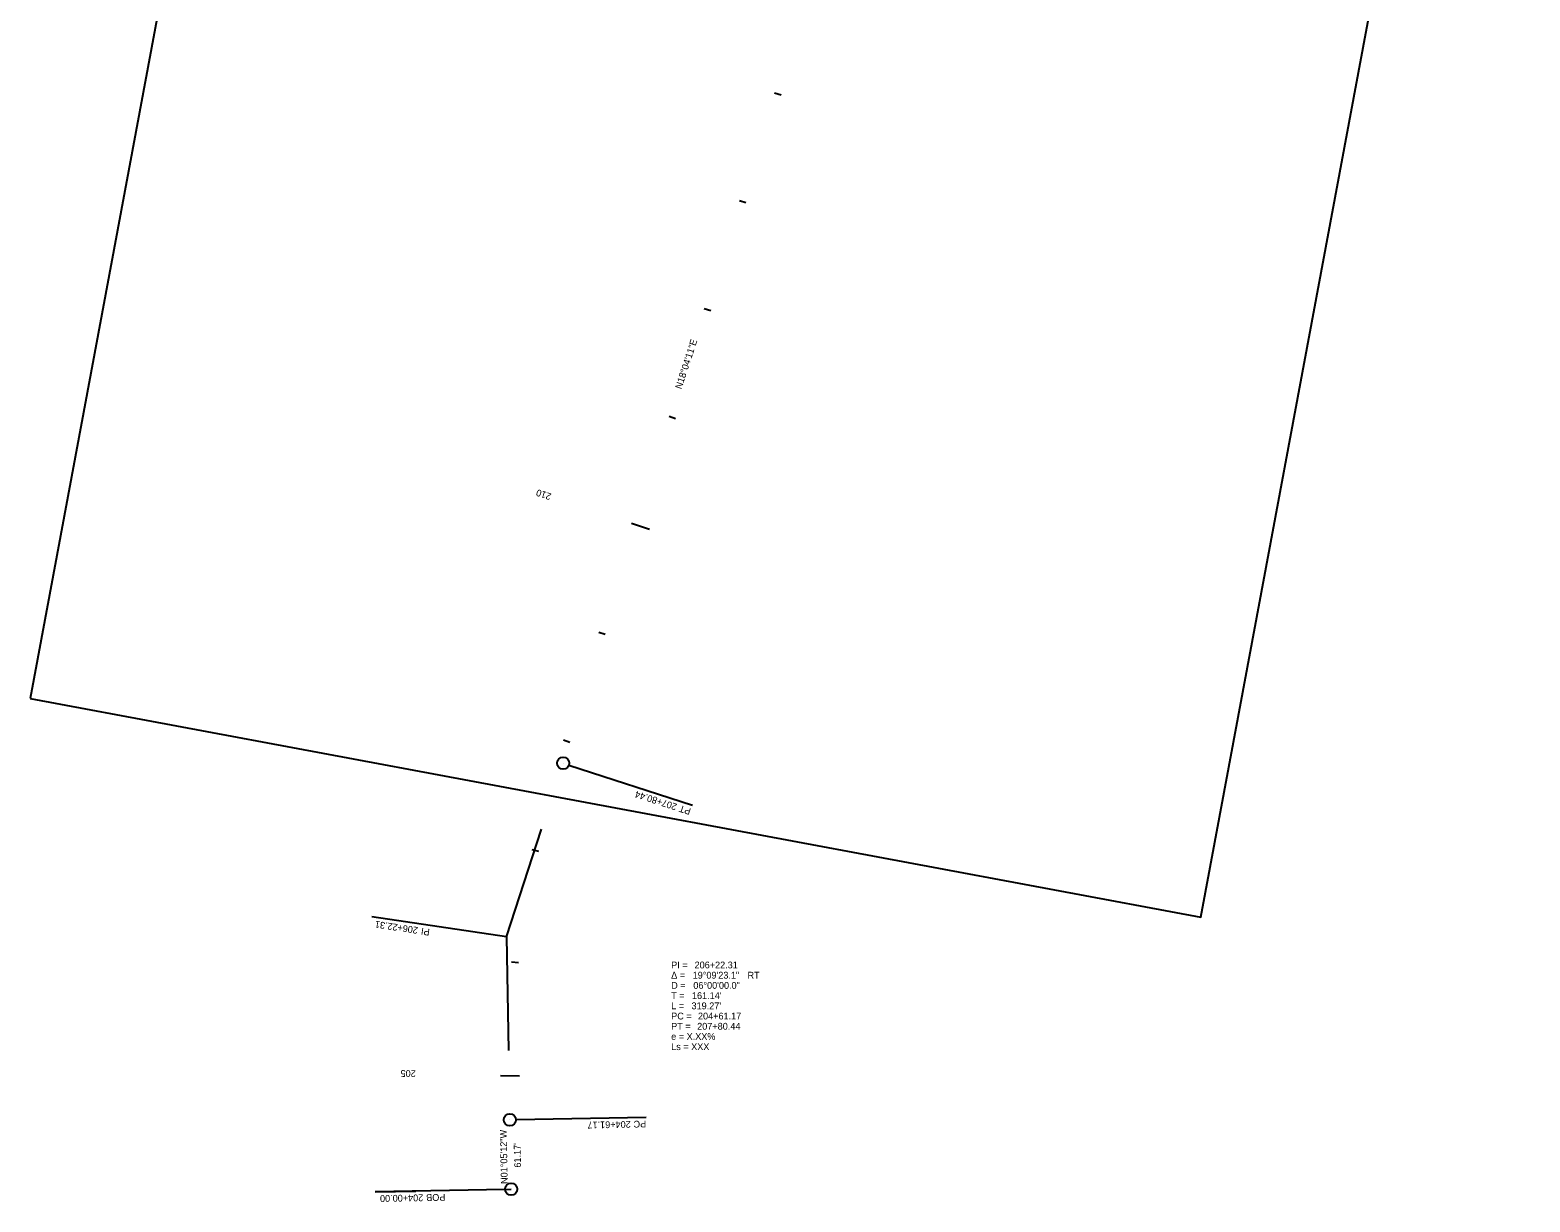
# Model space of a CAD drawing. Extents: x 1802364 to 1804577, y 572742 to 575010.
# Drawn here: x 1802779 to 1804101, y 572742 to 573774 of the extents above; entities that cross this region are included whole.
import ezdxf

# ---------------------------------------------------------------- set-up
doc = ezdxf.new("R2010")
doc.units = 0
for name, color, linetype in [('_CIVIL_CONSTRUCTION', 7, 'Continuous'), ('DSN_DRAIN_Analytics', 7, 'Continuous'), ('DSN_DRAIN_Storm-Sewer', 7, 'Continuous')]:
    doc.layers.add(name, color=color, linetype=linetype)

msp = doc.modelspace()

# ---------------------------------------------------------------- linework, layer by layer
at = {"layer": 'DSN_DRAIN_Analytics'}
for p, q in [((1803435.4, 573719.1), (1803441.1, 573717.3)), ((1803404.4, 573624.1), (1803410.1, 573622.2)), ((1803373.4, 573529), (1803379.1, 573527.1)), ((1803342.4, 573433.9), (1803348.1, 573432.1)), ((1803309.1, 573339.6), (1803325, 573334.4)), ((1803280.3, 573243.8), (1803286, 573241.9)), ((1803249.3, 573148.7), (1803255, 573146.9)), ((1803249, 573128.3), (1803249, 573128.3)), ((1803254, 573126.6), (1803363, 573091.1)), ((1803363, 573091.1), (1803363, 573091.1)), ((1803199, 572975.1), (1803230, 573070.2)), ((1803221.4, 573052.2), (1803227.3, 573050.8)), ((1803199, 572975.1), (1803080.3, 572992.8)), ((1803080.3, 572992.8), (1803080.3, 572992.8)), ((1803199, 572975.1), (1803200.9, 572875.1)), ((1803203.5, 572953.2), (1803209.5, 572952.5)), ((1803193.7, 572853), (1803210.5, 572852.6)), ((1803202, 572814), (1803202, 572814)), ((1803207.4, 572814.1), (1803322, 572816.3)), ((1803322, 572816.3), (1803322, 572816.3)), ((1803197.9, 572752.7), (1803083.2, 572750.5)), ((1803083.2, 572750.5), (1803119.2, 572751.2)), ((1803197.2, 572752.7), (1803203.2, 572752.8)), ((1803203.2, 572752.8), (1803203.2, 572752.8))]:
    msp.add_line(p, q, dxfattribs=at)
for centre in [(1803249, 573128.3), (1803202, 572814), (1803203.2, 572752.8)]:
    msp.add_circle(centre, 5.34, dxfattribs=at)
at = {"layer": 'DSN_DRAIN_Storm-Sewer'}
msp.add_lwpolyline([(1802779, 573185.2), (1803811.2, 572992.6), (1804101.3, 574547.6), (1803069.1, 574740.2)], close=True, dxfattribs=at)

# ---------------------------------------------------------------- texts
at = {"layer": '_CIVIL_CONSTRUCTION'}
msp.add_text("61.17'", height=6, rotation=91.0867, dxfattribs=at).set_placement((1803211.8, 572771.9))
at = {"layer": 'DSN_DRAIN_Analytics'}
for s, rotation, p in [('N18°04\'11"E', 71.9303, (1803353.2, 573457.4)), ('210', 161.9303, (1803239.1, 573365.6)), ('207+80.44', 161.9303, (1803349.8, 573092.2)), ('PT', 161.9303, (1803362.1, 573088.2)), ('206+22.31', 171.5085, (1803121.3, 572983.7)), ('PI ', 171.5085, (1803131.7, 572982.1)), ('205', 178.757, (1803119.1, 572857.6)), ('204+61.17', 181.0867, (1803308.5, 572813)), ('PC', 181.0867, (1803322.1, 572813.3)), ('N01°05\'12"W', 91.0867, (1803200.1, 572757.5)), ('204+00.00', 181.0867, (1803125.6, 572748.3)), ('POB ', 181.0867, (1803145.1, 572748.7))]:
    msp.add_text(s, height=6, rotation=rotation, dxfattribs=at).set_placement(p)
for s, p in [('Δ = ', (1803344.2, 572938.4)), ('PI = ', (1803344.2, 572947.4)), ('19°09\'23.1"', (1803363.1, 572938.4)), ('206+22.31', (1803364.8, 572947.4)), (' RT', (1803409.3, 572938.4)), ('D = ', (1803344.2, 572929.4)), ('06°00\'00.0"', (1803363.7, 572929.4)), ('T = ', (1803344.2, 572920.4)), ('L = ', (1803344.2, 572911.4)), ("319.27'", (1803362.1, 572911.4)), ("161.14'", (1803362.5, 572920.4)), ('PC = ', (1803344.2, 572902.4)), ('204+61.17', (1803367.8, 572902.4)), ('e = X.XX%', (1803344.2, 572884.4)), ('PT = ', (1803344.2, 572893.4)), ('207+80.44', (1803367.1, 572893.4)), ('Ls = XXX', (1803344.2, 572875.4))]:
    msp.add_text(s, height=6, dxfattribs=at).set_placement(p)

doc.saveas('drawing.dxf')
